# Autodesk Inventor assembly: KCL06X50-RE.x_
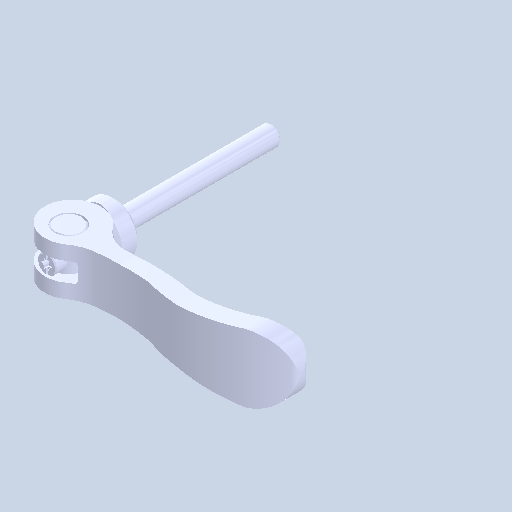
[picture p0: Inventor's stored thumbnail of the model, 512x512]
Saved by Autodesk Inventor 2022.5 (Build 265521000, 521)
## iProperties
Created: 2024-08
Part Number: KCL06X50-RE.x_
Document SubType Name: Assembly
Designer: ImaoCorp
Author: ImaoCorp
Sending System: SOLIDWORKS 2022-2022290
MC: AMD64
MC_MODEL: Intel64 Family 6 Model 60 Stepping 3, GenuineIntel
OS: Windows_NT
FRU: Parasolid Version 33.1, build 260,  4-25-2022
FORMAT: text
GUISE: transmit
KEY: FILEKCL06X50-RE.x_t
DATE: Thu Aug 29 10:50:04 2024
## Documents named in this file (5)
- Y:\5.更新分\2024年対応\1001_KCL\データ\kcl06x50-re\KCL06X50-RE.x_.iam
- Y:\5.更新分\2024年対応\1001_KCL\データ\kcl06x50-re\KCL06X50-RE_01.ipt
- Y:\5.更新分\2024年対応\1001_KCL\データ\kcl06x50-re\KCL06X50-RE_02.ipt
- Y:\5.更新分\2024年対応\1001_KCL\データ\kcl06x50-re\KCL06X50-RE_03.ipt
- Y:\5.更新分\2024年対応\1001_KCL\データ\kcl06x50-re\KCL06X50-RE_04.ipt
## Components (4 placed, 4 different names)
1. KCL06X50-RE_01
2. KCL06X50-RE_02
3. KCL06X50-RE_03
4. KCL06X50-RE_04
